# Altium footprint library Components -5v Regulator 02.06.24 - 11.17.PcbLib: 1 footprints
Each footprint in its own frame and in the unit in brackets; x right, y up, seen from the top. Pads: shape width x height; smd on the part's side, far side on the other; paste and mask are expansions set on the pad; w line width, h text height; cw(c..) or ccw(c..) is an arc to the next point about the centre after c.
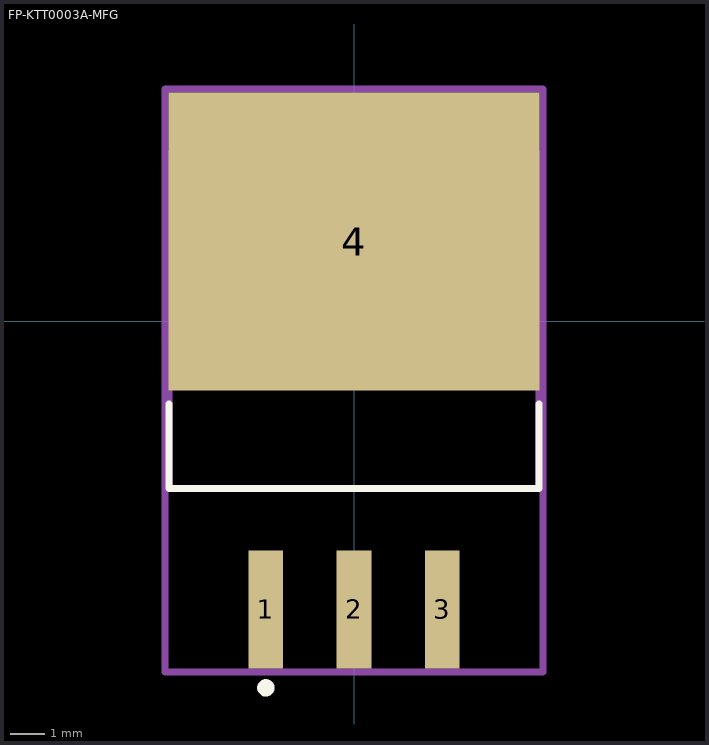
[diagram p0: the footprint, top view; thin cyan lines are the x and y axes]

## FP-KTT0003A-MFG [mm]
pads (4):
  rect 1x3.4 smd paste-1000 mask+0: 1(-2.54,-8.303) 2(0,-8.303) 3(2.54,-8.303)
  rect 10.7x8.6 smd paste-1000 mask+0: 4(0,2.298)
Top Overlay:
  circle w0.25: c-2.54,-10.562 r0.125
  lines w0.2: -5.335,-2.378 -5.335,-4.825 5.335,-4.825 5.335,-2.378
Top Paste:
  rectangle: -5.3,-1.953 5.3,6.548
  rectangle: 2.065,-9.952 3.015,-6.652
  rectangle: -0.475,-9.952 0.475,-6.652
  rectangle: -3.015,-9.952 -2.065,-6.652
Top Assembly:
  lines w0.2: -5.45,-10.102 -5.45,6.697 5.45,6.697 5.45,-10.102 -5.45,-10.102
  text ".Designator" at 0,-1.703 h1
Top 3D Body:
  lines w0.2: -5.335,-4.825 -5.335,4.825 5.335,4.825 5.335,-4.825 -5.335,-4.825
Top Courtyard:
  lines w0.2: -5.45,-10.102 -5.45,6.697 5.45,6.697 5.45,-10.102 -5.45,-10.102
Top Component Center:
  lines w0.1: -0.5,0 0.5,0 ; 0,-0.5 0,0.5
3D body "IC_Texas_Instruments_TL783CKTTR_eec.STEP": height 0.25, standoff 0, extent -5.45,-10.102 5.45,6.697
